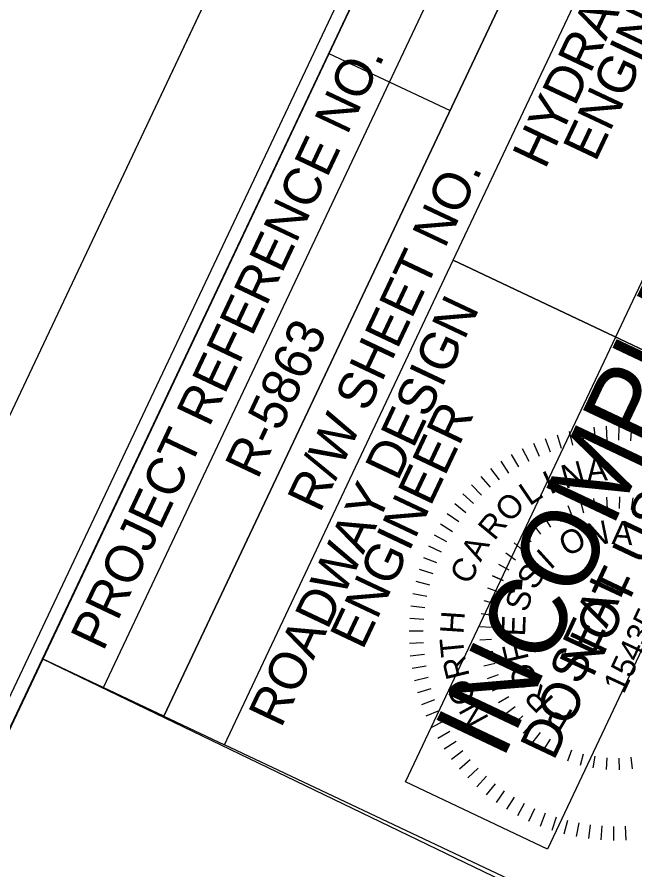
# Model space of a CAD drawing. Extents: x 556536 to 558250, y 505355 to 507347.
# Drawn here: x 557180.4 to 557295.8, y 507100.8 to 507260 of the extents above; entities that cross this region are included whole.
import ezdxf

# ---------------------------------------------------------------- set-up
doc = ezdxf.new("R2010")
doc.units = 0
for name, color, linetype in [('Prop Drainage Structure Box Number Symbol CELL', 7, 'Continuous'), ('Prop Drainage Structure Catch Basin Grate 840 03G CELL', 7, 'Continuous'), ('Prop Drainage Structure Tops and Inverts LABEL', 7, 'Continuous'), ('Prop Earthen Structure Base Ditch Lateral Detail Label', 7, 'Continuous'), ('Prop Earthen Structure Base Ditch Lateral with Rip Rap Detail Label', 7, 'Continuous'), ('Prop Earthen Structure Berm Ditch Detail Label', 7, 'Continuous'), ('Prop Erosion Rip Rap Class B', 7, 'Continuous'), ('Prop Erosion Rip Rap Pad at Outlet CELL', 7, 'Continuous')]:
    doc.layers.add(name, color=color, linetype=linetype)

msp = doc.modelspace()

# ---------------------------------------------------------------- linework, layer by layer
at = {"layer": 'Prop Drainage Structure Box Number Symbol CELL'}
msp.add_lwpolyline([(557273.74, 507333.49), (556561.61, 505826.81), (557515.52, 505375.94), (558227.66, 506882.62)], close=True, dxfattribs=at)
at = {"layer": 'Prop Drainage Structure Catch Basin Grate 840 03G CELL'}
msp.add_lwpolyline([(557798.52, 506240.88), (557748.79, 506156.98), (557718.06, 506089.72), (557705.43, 506089.79), (557646.19, 505968.9), (557731.53, 505869.1), (557643.42, 505687.13), (557512.37, 505750.31), (557008.7, 505860.07), (556630.15, 505965.86), (557185.22, 507140.23), (557323.61, 507073.55), (557372.9, 507178.95), (557443.19, 507138.35), (557473.73, 506971.77), (557393.31, 506960), (557425.46, 506933.59), (557889.73, 506539.36), (557955.03, 506511.13), (557971.08, 506460.75)], close=True, dxfattribs=at)
at = {"layer": 'Prop Drainage Structure Tops and Inverts LABEL'}
msp.add_lwpolyline([(557279.52, 507104.69), (557252.96, 507117.24), (557331.48, 507283.37), (557358.04, 507270.82)], close=True, dxfattribs=at)
at = {"layer": 'Prop Earthen Structure Base Ditch Lateral Detail Label'}
msp.add_lwpolyline([(557255.37, 507347.15), (556535.75, 505824.65), (557530.26, 505354.59), (558249.88, 506877.09)], close=True, dxfattribs=at)
at = {"layer": 'Prop Earthen Structure Berm Ditch Detail Label'}
msp.add_line((557255.37, 507347.15), (556535.75, 505824.65), dxfattribs=at)
at = {"layer": 'Prop Erosion Rip Rap Class B'}
for p, q in [((557196.57, 507134.87), (557282.05, 507315.74)), ((557207.87, 507129.53), (557293.36, 507310.39)), ((557207.87, 507129.53), (557293.36, 507310.39)), ((557238.7, 507253.27), (557261.31, 507242.59)), ((557261.92, 507214.64), (557363.59, 507166.59)), ((557207.87, 507129.53), (557219.17, 507124.19))]:
    msp.add_line(p, q, dxfattribs=at)
for points in [[(557270.71, 507321.1), (556629.72, 505964.95), (557579.02, 505516.26), (558220.01, 506872.41)], [(557185.22, 507140.23), (557270.71, 507321.1), (557293.36, 507310.39), (557207.87, 507129.53)], [(557261.92, 507214.64), (557304.66, 507305.05), (557406.37, 507256.98), (557363.64, 507166.57)], [(557219.17, 507124.19), (557261.92, 507214.64), (557363.64, 507166.57), (557320.88, 507076.11)]]:
    msp.add_lwpolyline(points, close=True, dxfattribs=at)
at = {"layer": 'Prop Erosion Rip Rap Pad at Outlet CELL'}
for p, q in [((557285.85, 507183.13), (557286.29, 507180.54)), ((557288.16, 507183.46), (557288.45, 507180.84)), ((557290.49, 507183.64), (557290.62, 507181)), ((557292.83, 507183.68), (557292.8, 507181.04)), ((557295.17, 507183.58), (557294.98, 507180.95)), ((557281.3, 507182.07), (557282.05, 507179.55)), ((557283.56, 507182.67), (557284.16, 507180.1)), ((557276.91, 507180.47), (557277.97, 507178.05)), ((557279.08, 507181.34), (557279.99, 507178.86)), ((557272.75, 507178.35), (557274.09, 507176.08)), ((557274.8, 507179.47), (557276, 507177.12)), ((557270.77, 507177.11), (557272.24, 507174.92)), ((557268.87, 507175.74), (557270.47, 507173.65)), ((557267.06, 507174.27), (557268.79, 507172.28)), ((557265.34, 507172.69), (557267.18, 507170.8)), ((557263.72, 507171.01), (557265.67, 507169.24)), ((557290.51, 507170.43), (557290.67, 507168.24)), ((557292.98, 507170.49), (557292.92, 507168.29)), ((557262.2, 507169.23), (557264.25, 507167.58)), ((557283.32, 507168.84), (557284.1, 507166.78)), ((557285.66, 507169.6), (557286.24, 507167.48)), ((557288.07, 507170.14), (557288.44, 507167.97)), ((557295.43, 507170.31), (557295.16, 507168.13)), ((557260.79, 507167.37), (557262.94, 507165.85)), ((557281.06, 507167.86), (557282.03, 507165.89)), ((557278.9, 507166.66), (557280.07, 507164.79)), ((557259.5, 507165.42), (557261.74, 507164.03)), ((557276.88, 507165.26), (557278.21, 507163.52)), ((557258.33, 507163.4), (557260.64, 507162.15)), ((557274.99, 507163.68), (557276.49, 507162.07)), ((557257.28, 507161.31), (557259.67, 507160.2)), ((557273.27, 507161.91), (557274.92, 507160.45)), ((557271.73, 507159.99), (557273.51, 507158.7)), ((557256.35, 507159.16), (557258.81, 507158.2)), ((557270.38, 507157.93), (557272.27, 507156.82)), ((557255.57, 507156.96), (557258.07, 507156.15)), ((557254.91, 507154.72), (557257.46, 507154.06)), ((557269.23, 507155.75), (557271.22, 507154.83)), ((557271.22, 507154.83), (557269.23, 507155.75)), ((557268.3, 507153.47), (557270.37, 507152.74)), ((557254.39, 507152.45), (557256.98, 507151.94)), ((557254.01, 507150.14), (557256.63, 507149.79)), ((557267.6, 507151.11), (557269.73, 507150.58)), ((557267.12, 507148.69), (557269.3, 507148.37)), ((557253.77, 507147.82), (557256.4, 507147.62)), ((557253.67, 507145.48), (557256.31, 507145.45)), ((557266.88, 507146.24), (557269.08, 507146.13)), ((557253.71, 507143.14), (557256.35, 507143.27)), ((557266.89, 507143.78), (557269.08, 507143.88)), ((557253.89, 507140.81), (557256.52, 507141.1)), ((557267.12, 507141.32), (557269.3, 507141.64)), ((557254.22, 507138.5), (557256.82, 507138.94)), ((557267.59, 507138.9), (557269.73, 507139.43)), ((557268.3, 507136.55), (557270.37, 507137.28)), ((557254.68, 507136.21), (557257.25, 507136.81)), ((557255.28, 507133.95), (557257.81, 507134.7)), ((557269.23, 507134.26), (557271.22, 507135.19)), ((557256.02, 507131.73), (557258.49, 507132.64)), ((557270.37, 507132.08), (557272.27, 507133.19)), ((557256.88, 507129.56), (557259.3, 507130.61)), ((557271.72, 507130.02), (557273.5, 507131.31)), ((557273.26, 507128.1), (557274.91, 507129.56)), ((557257.88, 507127.45), (557260.23, 507128.65)), ((557274.98, 507126.34), (557276.48, 507127.95)), ((557259, 507125.4), (557261.27, 507126.73)), ((557276.86, 507124.75), (557278.2, 507126.49)), ((557260.24, 507123.42), (557262.43, 507124.89)), ((557278.89, 507123.35), (557280.05, 507125.21)), ((557261.61, 507121.52), (557263.7, 507123.12)), ((557281.04, 507122.15), (557282.02, 507124.12)), ((557283.3, 507121.16), (557284.08, 507123.22)), ((557263.08, 507119.71), (557265.07, 507121.43)), ((557285.65, 507120.4), (557286.22, 507122.52)), ((557288.05, 507119.87), (557288.42, 507122.03)), ((557290.5, 507119.57), (557290.66, 507121.76)), ((557292.96, 507119.52), (557292.9, 507121.71)), ((557295.41, 507119.69), (557295.15, 507121.87)), ((557264.66, 507117.99), (557266.55, 507119.83)), ((557266.34, 507116.36), (557268.11, 507118.32)), ((557268.12, 507114.85), (557269.77, 507116.9)), ((557269.98, 507113.44), (557271.51, 507115.59)), ((557271.93, 507112.15), (557273.32, 507114.39)), ((557273.95, 507110.98), (557275.2, 507113.29)), ((557276.04, 507109.93), (557277.15, 507112.32)), ((557278.19, 507109), (557279.15, 507111.46)), ((557280.39, 507108.22), (557281.2, 507110.72)), ((557282.63, 507107.56), (557283.29, 507110.11)), ((557284.9, 507107.04), (557285.42, 507109.63)), ((557287.21, 507106.66), (557287.57, 507109.27)), ((557289.54, 507106.42), (557289.73, 507109.05)), ((557291.87, 507106.32), (557291.91, 507108.96)), ((557294.21, 507106.36), (557294.08, 507109))]:
    msp.add_line(p, q, dxfattribs=at)

# ---------------------------------------------------------------- texts
at = {"layer": 'Prop Drainage Structure Tops and Inverts LABEL'}
for s, height, p in [('INCOMPLETE PLANS', 14.4, (557271.07, 507121.08)), ('DO NOT USE FOR R/W ACQUISITION', 7.2, (557280.66, 507121.04))]:
    msp.add_text(s, height=height, rotation=64.7021, dxfattribs=at).set_placement(p)
at = {"layer": 'Prop Earthen Structure Base Ditch Lateral with Rip Rap Detail Label'}
msp.add_text('R-5863', height=7, rotation=64.7021, dxfattribs=at).set_placement((557225.36, 507173.55))
at = {"layer": 'Prop Erosion Rip Rap Class B'}
for s, p in [('HYDRAULICS', (557279.05, 507231.45)), ('ENGINEER', (557288.48, 507232.81)), ('PROJECT REFERENCE NO.', (557196.53, 507141.46)), ('R/W SHEET NO.', (557237, 507167.29)), ('ROADWAY DESIGN', (557229.75, 507127.14)), ('ENGINEER', (557244.98, 507141.71))]:
    msp.add_text(s, height=7, rotation=64.7021, dxfattribs=at).set_placement(p)
at = {"layer": 'Prop Erosion Rip Rap Pad at Outlet CELL'}
for s, height, rotation, p in [('N', 4.39, 15.3436, (557282.78, 507171.95)), ('A', 4.39, 5.5761, (557286.94, 507173.21)), ('I', 4.39, 24.6381, (557279.98, 507170.83)), ('L', 4.39, 34.2136, (557276.17, 507168.69)), ('O', 4.39, 47.3498, (557272.51, 507165.47)), ('R', 4.39, 50.4067, (557269.57, 507162.14)), ('N', 4.39, 11.5221, (557287.17, 507161.04)), ('A', 4.39, 356.2259, (557291.44, 507161.7)), ('O', 4.39, 26.8184, (557283.07, 507159.21)), ('A', 4.39, 62.416, (557267.03, 507158.2)), ('I', 4.39, 42.1146, (557280.03, 507156.72)), ('C', 4.39, 62.416, (557264.92, 507153.88)), ('S', 4.39, 57.4109, (557277.2, 507152.89)), ('SEAL', 6.591, 65.059, (557285.58, 507135.13)), ('S', 4.39, 72.7071, (557275.68, 507148.76)), ('15435', 4.391, 65.059, (557293.73, 507133.51)), ('H', 4.39, 86.1267, (557263.8, 507144.77)), ('E', 4.39, 88.0034, (557275.31, 507144.38)), ('T', 4.39, 95.5586, (557264.04, 507140.76)), ('F', 4.39, 103.2996, (557276.08, 507140.15)), ('R', 4.39, 103.7196, (557265.02, 507137.04)), ('O', 4.39, 118.5959, (557278.06, 507136.01)), ('O', 4.39, 116.7763, (557266.36, 507132.91)), ('R', 4.39, 133.8921, (557280.91, 507132.77)), ('N', 4.39, 118.7357, (557268.66, 507129.06)), ('P', 4.39, 149.1884, (557284.57, 507130.33))]:
    msp.add_text(s, height=height, rotation=rotation, dxfattribs=at).set_placement(p)

doc.saveas('drawing.dxf')
